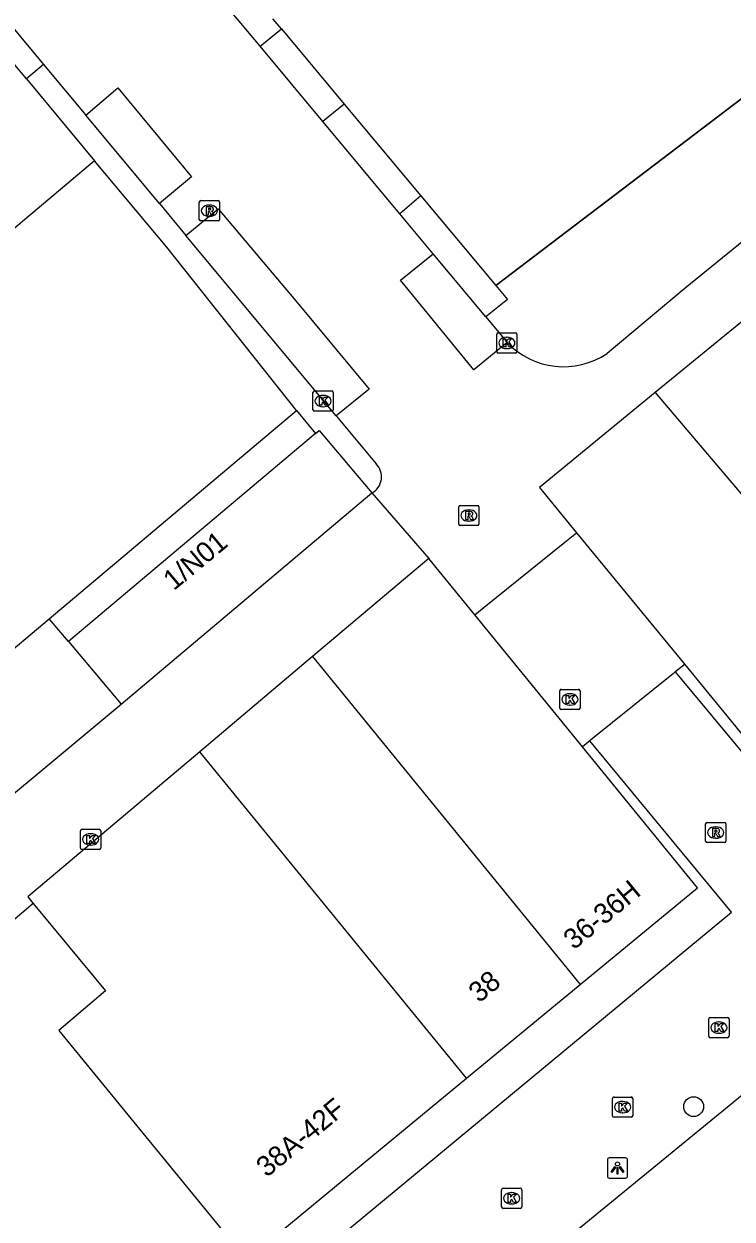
# Model space of a CAD drawing. Extents: x 161087 to 161922, y 382574 to 383873.
# Drawn here: x 161314.7 to 161349.7, y 383087.7 to 383146.8 of the extents above; entities that cross this region are included whole.
import ezdxf

# ---------------------------------------------------------------- set-up
doc = ezdxf.new("R2010")
doc.units = 0
for name, color, linetype in [('IMGEO_Boom', 7, 'Continuous'), ('IMGEO_Kolk', 7, 'Continuous'), ('IMGEO_Lichtpunt', 7, 'Continuous'), ('IMGEO_Muur', 7, 'Continuous'), ('IMGEO_Pand', 7, 'Continuous'), ('IMGEO_Pand_nummerreeks', 7, 'Continuous'), ('IMGEO_Parkeervlak_open', 7, 'Continuous'), ('IMGEO_Rijbaan_lokaal_open', 7, 'Continuous'), ('IMGEO_Rioolput', 7, 'Continuous'), ('IMGEO_Voetgangersgebied_open', 7, 'Continuous'), ('IMGEO_Voetpad_open', 7, 'Continuous')]:
    doc.layers.add(name, color=color, linetype=linetype)

msp = doc.modelspace()

# ---------------------------------------------------------------- linework, layer by layer
at = {"layer": 'IMGEO_Boom'}
msp.add_circle((161347.806, 383093.222), 0.489, dxfattribs=at)
at = {"layer": 'IMGEO_Kolk'}
for p, q in [((161338.063, 383130.574), (161338.063, 383131.426)), ((161338.138, 383131.5), (161338.99, 383131.5)), ((161339.064, 383131.426), (161339.064, 383130.574)), ((161338.551, 383131.28), (161338.576, 383131.28)), ((161338.99, 383130.5), (161338.138, 383130.5)), ((161338.574, 383130.72), (161338.549, 383130.72)), ((161328.969, 383127.696), (161328.969, 383128.548)), ((161329.044, 383128.622), (161329.896, 383128.622)), ((161329.457, 383128.402), (161329.482, 383128.402)), ((161329.97, 383128.548), (161329.97, 383127.696)), ((161329.48, 383127.842), (161329.455, 383127.842)), ((161329.896, 383127.622), (161329.044, 383127.622)), ((161341.182, 383112.938), (161341.182, 383113.79)), ((161341.257, 383113.864), (161342.109, 383113.864)), ((161341.67, 383113.644), (161341.695, 383113.644)), ((161342.183, 383113.79), (161342.183, 383112.938)), ((161341.693, 383113.084), (161341.668, 383113.084)), ((161342.109, 383112.864), (161341.257, 383112.864)), ((161317.467, 383106.014), (161317.467, 383106.866)), ((161317.542, 383106.94), (161318.394, 383106.94)), ((161317.955, 383106.72), (161317.98, 383106.72)), ((161318.468, 383106.866), (161318.468, 383106.014)), ((161318.394, 383105.94), (161317.542, 383105.94)), ((161317.978, 383106.16), (161317.953, 383106.16)), ((161348.631, 383097.633), (161349.483, 383097.633)), ((161348.556, 383096.707), (161348.556, 383097.559)), ((161349.044, 383097.413), (161349.069, 383097.413)), ((161349.557, 383097.559), (161349.557, 383096.707)), ((161349.483, 383096.633), (161348.631, 383096.633)), ((161349.067, 383096.853), (161349.042, 383096.853)), ((161343.792, 383092.773), (161343.792, 383093.625)), ((161343.867, 383093.699), (161344.719, 383093.699)), ((161344.793, 383093.625), (161344.793, 383092.773)), ((161344.303, 383092.919), (161344.278, 383092.919)), ((161344.28, 383093.479), (161344.305, 383093.479)), ((161344.719, 383092.699), (161343.867, 383092.699)), ((161338.301, 383088.263), (161338.301, 383089.115)), ((161338.376, 383089.189), (161339.228, 383089.189)), ((161338.789, 383088.969), (161338.814, 383088.969)), ((161339.302, 383089.115), (161339.302, 383088.263)), ((161339.228, 383088.189), (161338.376, 383088.189)), ((161338.812, 383088.409), (161338.787, 383088.409))]:
    msp.add_line(p, q, dxfattribs=at)
for points in [[(161338.063, 383130.574), (161338.063, 383131.426)], [(161338.138, 383131.5), (161338.99, 383131.5)], [(161339.064, 383131.426), (161339.064, 383130.574)], [(161338.384, 383131.2), (161338.507, 383131.2), (161338.507, 383131.049), (161338.637, 383131.2), (161338.801, 383131.2), (161338.655, 383131.049), (161338.808, 383130.8), (161338.656, 383130.8), (161338.571, 383130.964), (161338.507, 383130.897), (161338.507, 383130.8), (161338.384, 383130.8), (161338.384, 383131.2)], [(161338.99, 383130.5), (161338.138, 383130.5)], [(161328.969, 383127.696), (161328.969, 383128.548)], [(161329.044, 383128.622), (161329.896, 383128.622)], [(161329.97, 383128.548), (161329.97, 383127.696)], [(161329.29, 383128.322), (161329.413, 383128.322), (161329.413, 383128.171), (161329.543, 383128.322), (161329.707, 383128.322), (161329.561, 383128.171), (161329.714, 383127.922), (161329.562, 383127.922), (161329.477, 383128.086), (161329.413, 383128.019), (161329.413, 383127.922), (161329.29, 383127.922), (161329.29, 383128.322)], [(161329.896, 383127.622), (161329.044, 383127.622)], [(161341.182, 383112.938), (161341.182, 383113.79)], [(161341.257, 383113.864), (161342.109, 383113.864)], [(161342.183, 383113.79), (161342.183, 383112.938)], [(161341.503, 383113.564), (161341.626, 383113.564), (161341.626, 383113.413), (161341.756, 383113.564), (161341.92, 383113.564), (161341.774, 383113.413), (161341.927, 383113.164), (161341.775, 383113.164), (161341.69, 383113.328), (161341.626, 383113.261), (161341.626, 383113.164), (161341.503, 383113.164), (161341.503, 383113.564)], [(161342.109, 383112.864), (161341.257, 383112.864)], [(161317.467, 383106.014), (161317.467, 383106.866)], [(161317.542, 383106.94), (161318.394, 383106.94)], [(161317.788, 383106.64), (161317.911, 383106.64), (161317.911, 383106.489), (161318.041, 383106.64), (161318.205, 383106.64), (161318.059, 383106.489), (161318.212, 383106.24), (161318.06, 383106.24), (161317.975, 383106.404), (161317.911, 383106.337), (161317.911, 383106.24), (161317.788, 383106.24), (161317.788, 383106.64)], [(161318.468, 383106.866), (161318.468, 383106.014)], [(161318.394, 383105.94), (161317.542, 383105.94)], [(161348.631, 383097.633), (161349.483, 383097.633)], [(161348.556, 383096.707), (161348.556, 383097.559)], [(161348.877, 383097.333), (161349, 383097.333), (161349, 383097.182), (161349.13, 383097.333), (161349.294, 383097.333), (161349.148, 383097.182), (161349.301, 383096.933), (161349.149, 383096.933), (161349.064, 383097.097), (161349, 383097.03), (161349, 383096.933), (161348.877, 383096.933), (161348.877, 383097.333)], [(161349.557, 383097.559), (161349.557, 383096.707)], [(161349.483, 383096.633), (161348.631, 383096.633)], [(161343.792, 383092.773), (161343.792, 383093.625)], [(161343.867, 383093.699), (161344.719, 383093.699)], [(161344.793, 383093.625), (161344.793, 383092.773)], [(161344.113, 383093.399), (161344.236, 383093.399), (161344.236, 383093.248), (161344.366, 383093.399), (161344.53, 383093.399), (161344.384, 383093.248), (161344.537, 383092.999), (161344.385, 383092.999), (161344.3, 383093.163), (161344.236, 383093.096), (161344.236, 383092.999), (161344.113, 383092.999), (161344.113, 383093.399)], [(161344.719, 383092.699), (161343.867, 383092.699)], [(161338.301, 383088.263), (161338.301, 383089.115)], [(161338.376, 383089.189), (161339.228, 383089.189)], [(161338.622, 383088.889), (161338.745, 383088.889), (161338.745, 383088.738), (161338.875, 383088.889), (161339.039, 383088.889), (161338.893, 383088.738), (161339.046, 383088.489), (161338.894, 383088.489), (161338.809, 383088.653), (161338.745, 383088.586), (161338.745, 383088.489), (161338.622, 383088.489), (161338.622, 383088.889)], [(161339.302, 383089.115), (161339.302, 383088.263)], [(161339.228, 383088.189), (161338.376, 383088.189)]]:
    msp.add_lwpolyline(points, dxfattribs=at)
for centre, start, end in [((161338.14, 383131.424), 91.55205, 178.44795), ((161338.14, 383131.424), 91.55205, 178.44795), ((161338.988, 383131.424), 1.55205, 88.44795), ((161338.988, 383131.424), 1.55205, 88.44795), ((161338.14, 383130.576), 181.55205, 268.44795), ((161338.14, 383130.576), 181.55205, 268.44795), ((161338.988, 383130.576), 271.55205, 358.44795), ((161338.988, 383130.576), 271.55205, 358.44795), ((161329.046, 383128.546), 91.55205, 178.44795), ((161329.046, 383128.546), 91.55205, 178.44795), ((161329.894, 383128.546), 1.55205, 88.44795), ((161329.894, 383128.546), 1.55205, 88.44795), ((161329.046, 383127.698), 181.55205, 268.44795), ((161329.046, 383127.698), 181.55205, 268.44795), ((161329.894, 383127.698), 271.55205, 358.44795), ((161329.894, 383127.698), 271.55205, 358.44795), ((161341.259, 383113.788), 91.55205, 178.44795), ((161341.259, 383113.788), 91.55205, 178.44795), ((161342.107, 383113.788), 1.55205, 88.44795), ((161342.107, 383113.788), 1.55205, 88.44795), ((161341.259, 383112.94), 181.55205, 268.44795), ((161341.259, 383112.94), 181.55205, 268.44795), ((161342.107, 383112.94), 271.55205, 358.44795), ((161342.107, 383112.94), 271.55205, 358.44795), ((161317.544, 383106.864), 91.55205, 178.44795), ((161317.544, 383106.864), 91.55205, 178.44795), ((161318.392, 383106.864), 1.55205, 88.44795), ((161318.392, 383106.864), 1.55205, 88.44795), ((161317.544, 383106.016), 181.55205, 268.44795), ((161317.544, 383106.016), 181.55205, 268.44795), ((161318.392, 383106.016), 271.55205, 358.44795), ((161318.392, 383106.016), 271.55205, 358.44795), ((161348.633, 383097.557), 91.55205, 178.44795), ((161348.633, 383097.557), 91.55205, 178.44795), ((161349.481, 383097.557), 1.55205, 88.44795), ((161349.481, 383097.557), 1.55205, 88.44795), ((161348.633, 383096.709), 181.55205, 268.44795), ((161348.633, 383096.709), 181.55205, 268.44795), ((161349.481, 383096.709), 271.55205, 358.44795), ((161349.481, 383096.709), 271.55205, 358.44795), ((161343.869, 383093.623), 91.55205, 178.44795), ((161343.869, 383093.623), 91.55205, 178.44795), ((161344.717, 383093.623), 1.55205, 88.44795), ((161344.717, 383093.623), 1.55205, 88.44795), ((161343.869, 383092.775), 181.55205, 268.44795), ((161343.869, 383092.775), 181.55205, 268.44795), ((161344.717, 383092.775), 271.55205, 358.44795), ((161344.717, 383092.775), 271.55205, 358.44795), ((161338.378, 383089.113), 91.55205, 178.44795), ((161338.378, 383089.113), 91.55205, 178.44795), ((161339.226, 383089.113), 1.55205, 88.44795), ((161339.226, 383089.113), 1.55205, 88.44795), ((161338.378, 383088.265), 181.55205, 268.44795), ((161338.378, 383088.265), 181.55205, 268.44795), ((161339.226, 383088.265), 271.55205, 358.44795), ((161339.226, 383088.265), 271.55205, 358.44795)]:
    msp.add_arc(centre, 0.0765, start, end, dxfattribs=at)
for centre, major_axis, ratio, start_param, end_param in [((161338.55, 383131), (-0.387, 0.002), 0.722429, 4.712389, 7.853982), ((161338.575, 383131), (-0.39, 0.002), 0.717154, 1.570796, 4.712389), ((161329.456, 383128.122), (-0.387, 0.002), 0.722429, 4.712389, 7.853982), ((161329.481, 383128.122), (-0.39, 0.002), 0.717154, 1.570796, 4.712389), ((161341.669, 383113.364), (-0.387, 0.002), 0.722429, 4.712389, 7.853982), ((161341.694, 383113.364), (-0.39, 0.002), 0.717154, 1.570796, 4.712389), ((161317.954, 383106.44), (-0.387, 0.002), 0.722429, 4.712389, 7.853982), ((161317.979, 383106.44), (-0.39, 0.002), 0.717154, 1.570796, 4.712389), ((161349.043, 383097.133), (-0.387, 0.002), 0.722429, 4.712389, 7.853982), ((161349.068, 383097.133), (-0.39, 0.002), 0.717154, 1.570796, 4.712389), ((161344.279, 383093.199), (-0.387, 0.002), 0.722429, 4.712389, 7.853982), ((161344.304, 383093.199), (-0.39, 0.002), 0.717154, 1.570796, 4.712389), ((161338.788, 383088.689), (-0.387, 0.002), 0.722429, 4.712389, 7.853982), ((161338.813, 383088.689), (-0.39, 0.002), 0.717154, 1.570796, 4.712389)]:
    msp.add_ellipse(centre, major_axis=major_axis, ratio=ratio, start_param=start_param, end_param=end_param, dxfattribs=at)
at = {"layer": 'IMGEO_Lichtpunt'}
for p, q in [((161343.539, 383090.591), (161343.539, 383089.784)), ((161343.539, 383090.591), (161343.539, 383089.784)), ((161344.441, 383090.686), (161343.633, 383090.686)), ((161344.441, 383090.686), (161343.633, 383090.686)), ((161344.535, 383089.784), (161344.535, 383090.591)), ((161344.535, 383089.784), (161344.535, 383090.591)), ((161343.633, 383089.69), (161344.441, 383089.69)), ((161343.633, 383089.69), (161344.441, 383089.69))]:
    msp.add_line(p, q, dxfattribs=at)
for points in [[(161343.913, 383090.255), (161343.952, 383090.227), (161343.764, 383089.965), (161343.726, 383089.992), (161343.913, 383090.255)], [(161344.015, 383090.207), (161344.062, 383090.207), (161344.062, 383089.885), (161344.015, 383089.885), (161344.015, 383090.207)], [(161344.125, 383090.227), (161344.163, 383090.254), (161344.35, 383089.992), (161344.311, 383089.964), (161344.125, 383090.227)]]:
    msp.add_lwpolyline(points, dxfattribs=at)
msp.add_circle((161344.038, 383090.389), 0.0994, dxfattribs=at)
for centre, start, end in [((161343.633, 383090.591), 90, 180), ((161343.633, 383090.591), 90, 180), ((161344.441, 383090.591), 0, 90), ((161344.441, 383090.591), 0, 90), ((161343.633, 383089.784), 180, 270), ((161343.633, 383089.784), 180, 270), ((161344.441, 383089.784), 270, 0), ((161344.441, 383089.784), 270, 360)]:
    msp.add_arc(centre, 0.0946, start, end, dxfattribs=at)
at = {"layer": 'IMGEO_Muur'}
msp.add_lwpolyline([(161338.02, 383133.832), (161352.139, 383144.565)], dxfattribs=at)
at = {"layer": 'IMGEO_Pand'}
for points in [[(161318.155, 383140.007), (161303.657, 383127.806), (161297.243, 383122.411), (161296.75, 383123.041)], [(161328.147, 383127.651), (161321.746, 383135.741), (161318.155, 383140.007)], [(161351.5, 383133.112), (161345.91, 383128.541)], [(161345.91, 383128.541), (161340.173, 383123.848), (161342.01, 383121.612)], [(161345.91, 383128.541), (161356.619, 383115.911)], [(161315.91, 383117.352), (161328.147, 383127.651)], [(161329.098, 383126.516), (161329.283, 383126.672), (161331.884, 383123.579)], [(161329.098, 383126.516), (161316.874, 383116.227)], [(161319.475, 383113.135), (161331.884, 383123.579)], [(161342.01, 383121.612), (161347.363, 383115.097)], [(161334.699, 383120.333), (161328.949, 383115.484)], [(161336.976, 383117.545), (161334.699, 383120.333)], [(161306.597, 383109.514), (161315.91, 383117.352)], [(161342.3, 383111.027), (161342.167, 383111.191), (161336.976, 383117.545)], [(161316.874, 383116.227), (161319.475, 383113.135)], [(161328.949, 383115.484), (161323.371, 383110.78)], [(161328.949, 383115.484), (161342.197, 383099.261)], [(161347.363, 383115.097), (161348.48, 383113.738), (161349.746, 383112.193), (161350.691, 383111.04), (161353.296, 383113.18)], [(161323.371, 383110.78), (161314.857, 383103.599), (161315.131, 383103.273)], [(161336.573, 383094.624), (161323.371, 383110.78)], [(161342.197, 383099.261), (161348.002, 383104.048), (161342.3, 383111.027)], [(161315.131, 383103.273), (161312.979, 383101.462)], [(161315.131, 383103.273), (161318.705, 383098.955), (161316.388, 383096.985), (161325.68, 383085.643)], [(161336.573, 383094.624), (161342.197, 383099.261)], [(161325.68, 383085.643), (161336.573, 383094.624)]]:
    msp.add_lwpolyline(points, dxfattribs=at)
at = {"layer": 'IMGEO_Parkeervlak_open'}
for points in [[(161352.139, 383144.565), (161338.02, 383133.832)], [(161337.522, 383132.286), (161338.578, 383131.016)]]:
    msp.add_lwpolyline(points, dxfattribs=at)
at = {"layer": 'IMGEO_Rijbaan_lokaal_open'}
for points in [[(161311.777, 383149.418), (161315.642, 383144.775)], [(161326.36, 383145.671), (161323.832, 383148.703), (161323.335, 383149.299)], [(161329.465, 383141.948), (161326.36, 383145.671)], [(161315.642, 383144.775), (161317.729, 383142.268)], [(161317.729, 383142.268), (161319.315, 383143.611), (161322.96, 383139.22), (161321.375, 383137.889)], [(161333.271, 383137.384), (161329.465, 383141.948)], [(161355.558, 383140.385), (161351.874, 383137.347), (161347.38, 383133.706), (161343.527, 383130.482)], [(161321.375, 383137.889), (161322.685, 383136.315)], [(161322.685, 383136.315), (161324.276, 383137.635), (161328.101, 383133.1), (161331.755, 383128.708), (161330.12, 383127.386)], [(161334.914, 383135.414), (161333.271, 383137.384)], [(161338.578, 383131.016), (161336.936, 383129.67), (161333.299, 383134.098), (161334.914, 383135.414)], [(161330.12, 383127.386), (161332.094, 383125.015)], [(161331.884, 383123.579), (161334.699, 383120.333)], [(161336.976, 383117.545), (161337.445, 383117.924), (161341.44, 383121.151), (161342.01, 383121.612)], [(161347.363, 383115.097), (161346.896, 383114.722)], [(161346.896, 383114.722), (161346.807, 383114.65), (161342.789, 383111.42), (161342.668, 383111.323)], [(161309.985, 383105.238), (161319.475, 383113.135)], [(161342.668, 383111.323), (161342.3, 383111.027)], [(161357.76, 383102.637), (161353.934, 383096.833), (161331.379, 383078.376), (161324.754, 383073.591), (161319.89, 383069.645)]]:
    msp.add_lwpolyline(points, dxfattribs=at)
for centre, radius, start, end in [((161341.369, 383133.684), 3.861, 223.7046, 303.97855), ((161331.47, 383124.373), 0.895, 297.52711, 45.83303)]:
    msp.add_arc(centre, radius, start, end, dxfattribs=at)
at = {"layer": 'IMGEO_Rioolput'}
for p, q in [((161323.345, 383137.111), (161323.345, 383137.963)), ((161323.42, 383138.037), (161324.272, 383138.037)), ((161324.346, 383137.963), (161324.346, 383137.111)), ((161323.856, 383137.257), (161323.831, 383137.257)), ((161323.833, 383137.817), (161323.858, 383137.817)), ((161324.272, 383137.037), (161323.42, 383137.037)), ((161336.182, 383122.037), (161336.182, 383122.889)), ((161336.257, 383122.963), (161337.109, 383122.963)), ((161336.67, 383122.743), (161336.695, 383122.743)), ((161337.183, 383122.889), (161337.183, 383122.037)), ((161337.109, 383121.963), (161336.257, 383121.963)), ((161336.693, 383122.183), (161336.668, 383122.183)), ((161348.395, 383106.355), (161348.395, 383107.207)), ((161348.47, 383107.281), (161349.322, 383107.281)), ((161349.396, 383107.207), (161349.396, 383106.355)), ((161348.906, 383106.501), (161348.881, 383106.501)), ((161348.883, 383107.061), (161348.908, 383107.061)), ((161349.322, 383106.281), (161348.47, 383106.281))]:
    msp.add_line(p, q, dxfattribs=at)
for points in [[(161323.345, 383137.111), (161323.345, 383137.963)], [(161323.42, 383138.037), (161324.272, 383138.037)], [(161324.346, 383137.963), (161324.346, 383137.111)], [(161323.934, 383137.735), (161323.682, 383137.737), (161323.682, 383137.337)], [(161323.682, 383137.337), (161323.806, 383137.337), (161323.806, 383137.499), (161323.817, 383137.499)], [(161323.86, 383137.656), (161323.806, 383137.656), (161323.806, 383137.575)], [(161323.806, 383137.575), (161323.858, 383137.575)], [(161323.864, 383137.47), (161323.935, 383137.337), (161324.075, 383137.337), (161324.01, 383137.463)], [(161324.272, 383137.037), (161323.42, 383137.037)], [(161336.182, 383122.037), (161336.182, 383122.889)], [(161336.257, 383122.963), (161337.109, 383122.963)], [(161336.771, 383122.661), (161336.519, 383122.663), (161336.519, 383122.263)], [(161336.697, 383122.582), (161336.643, 383122.582), (161336.643, 383122.501)], [(161336.643, 383122.501), (161336.695, 383122.501)], [(161337.183, 383122.889), (161337.183, 383122.037)], [(161337.109, 383121.963), (161336.257, 383121.963)], [(161336.519, 383122.263), (161336.643, 383122.263), (161336.643, 383122.425), (161336.654, 383122.425)], [(161336.701, 383122.396), (161336.772, 383122.263), (161336.912, 383122.263), (161336.847, 383122.389)], [(161348.395, 383106.355), (161348.395, 383107.207)], [(161348.47, 383107.281), (161349.322, 383107.281)], [(161349.396, 383107.207), (161349.396, 383106.355)], [(161348.984, 383106.979), (161348.732, 383106.981), (161348.732, 383106.581)], [(161348.732, 383106.581), (161348.856, 383106.581), (161348.856, 383106.743), (161348.867, 383106.743)], [(161348.91, 383106.9), (161348.856, 383106.9), (161348.856, 383106.819)], [(161348.856, 383106.819), (161348.908, 383106.819)], [(161348.914, 383106.714), (161348.985, 383106.581), (161349.125, 383106.581), (161349.06, 383106.707)], [(161349.322, 383106.281), (161348.47, 383106.281)]]:
    msp.add_lwpolyline(points, dxfattribs=at)
for centre, radius, start, end in [((161323.422, 383137.961), 0.0765, 91.55205, 178.44795), ((161323.422, 383137.961), 0.0765, 91.55205, 178.44795), ((161324.27, 383137.961), 0.0765, 1.55205, 88.44795), ((161324.27, 383137.961), 0.0765, 1.55205, 88.44795), ((161323.816, 383137.446), 0.0533, 26.02933, 88.69889), ((161323.842, 383137.764), 0.19, 274.7715, 282.96867), ((161323.866, 383137.56), 0.0964, 77.00612, 93.18647), ((161323.88, 383137.617), 0.0378, 276.66336, 79.67722), ((161323.933, 383137.625), 0.109, 350.36119, 89.41601), ((161323.931, 383137.625), 0.112, 277.58423, 350.98172), ((161323.915, 383137.41), 0.108, 29.51342, 73.79051), ((161323.422, 383137.113), 0.0765, 181.55205, 268.44795), ((161323.422, 383137.113), 0.0765, 181.55205, 268.44795), ((161324.27, 383137.113), 0.0765, 271.55205, 358.44795), ((161324.27, 383137.113), 0.0765, 271.55205, 358.44795), ((161336.259, 383122.887), 0.0765, 91.55205, 178.44795), ((161336.259, 383122.887), 0.0765, 91.55205, 178.44795), ((161336.679, 383122.69), 0.19, 274.7715, 282.96867), ((161336.703, 383122.486), 0.0964, 77.00612, 93.18647), ((161336.717, 383122.543), 0.0378, 276.66336, 79.67722), ((161336.77, 383122.551), 0.109, 350.36119, 89.41601), ((161336.768, 383122.551), 0.112, 277.58423, 350.98172), ((161337.107, 383122.887), 0.0765, 1.55205, 88.44795), ((161337.107, 383122.887), 0.0765, 1.55205, 88.44795), ((161336.259, 383122.039), 0.0765, 181.55205, 268.44795), ((161336.259, 383122.039), 0.0765, 181.55205, 268.44795), ((161336.653, 383122.372), 0.0533, 26.02933, 88.69889), ((161336.752, 383122.336), 0.108, 29.51342, 73.79051), ((161337.107, 383122.039), 0.0765, 271.55205, 358.44795), ((161337.107, 383122.039), 0.0765, 271.55205, 358.44795), ((161348.472, 383107.205), 0.0765, 91.55205, 178.44795), ((161348.472, 383107.205), 0.0765, 91.55205, 178.44795), ((161349.32, 383107.205), 0.0765, 1.55205, 88.44795), ((161349.32, 383107.205), 0.0765, 1.55205, 88.44795), ((161348.866, 383106.69), 0.0533, 26.02933, 88.69889), ((161348.892, 383107.008), 0.19, 274.7715, 282.96867), ((161348.916, 383106.804), 0.0964, 77.00612, 93.18647), ((161348.93, 383106.861), 0.0378, 276.66336, 79.67722), ((161348.983, 383106.869), 0.109, 350.36119, 89.41601), ((161348.981, 383106.869), 0.112, 277.58423, 350.98172), ((161348.965, 383106.654), 0.108, 29.51342, 73.79051), ((161348.472, 383106.357), 0.0765, 181.55205, 268.44795), ((161348.472, 383106.357), 0.0765, 181.55205, 268.44795), ((161349.32, 383106.357), 0.0765, 271.55205, 358.44795), ((161349.32, 383106.357), 0.0765, 271.55205, 358.44795)]:
    msp.add_arc(centre, radius, start, end, dxfattribs=at)
for centre, major_axis, ratio, start_param, end_param in [((161323.832, 383137.537), (-0.387, 0.002), 0.722429, 4.712389, 7.853982), ((161323.857, 383137.537), (-0.39, 0.002), 0.717154, 1.570796, 4.712389), ((161336.669, 383122.463), (-0.387, 0.002), 0.722429, 4.712389, 7.853982), ((161336.694, 383122.463), (-0.39, 0.002), 0.717154, 1.570796, 4.712389), ((161348.882, 383106.781), (-0.387, 0.002), 0.722429, 4.712389, 7.853982), ((161348.907, 383106.781), (-0.39, 0.002), 0.717154, 1.570796, 4.712389)]:
    msp.add_ellipse(centre, major_axis=major_axis, ratio=ratio, start_param=start_param, end_param=end_param, dxfattribs=at)
at = {"layer": 'IMGEO_Voetgangersgebied_open'}
for points in [[(161346.896, 383114.722), (161350.565, 383110.309), (161353.567, 383112.777)], [(161315.817, 383074.812), (161349.672, 383102.844), (161342.668, 383111.323)]]:
    msp.add_lwpolyline(points, dxfattribs=at)
at = {"layer": 'IMGEO_Voetpad_open'}
for points in [[(161314.789, 383144.056), (161310.902, 383148.73)], [(161327.407, 383146.528), (161326.987, 383147.03)], [(161326.36, 383145.671), (161327.407, 383146.528)], [(161327.407, 383146.528), (161330.518, 383142.806)], [(161315.642, 383144.775), (161314.789, 383144.056)], [(161314.789, 383144.056), (161318.155, 383140.007)], [(161330.518, 383142.806), (161329.465, 383141.948)], [(161330.518, 383142.806), (161334.311, 383138.269)], [(161321.375, 383137.889), (161317.729, 383142.268)], [(161334.311, 383138.269), (161333.271, 383137.384)], [(161334.311, 383138.269), (161338.02, 383133.832)], [(161330.12, 383127.386), (161322.685, 383136.315)], [(161337.522, 383132.286), (161334.914, 383135.414)], [(161338.02, 383133.832), (161338.597, 383133.149), (161337.522, 383132.286)], [(161328.147, 383127.651), (161329.098, 383126.516)], [(161316.874, 383116.227), (161315.91, 383117.352)]]:
    msp.add_lwpolyline(points, dxfattribs=at)

# ---------------------------------------------------------------- texts
at = {"layer": 'IMGEO_Pand_nummerreeks'}
for s, rotation, p in [('1/N01', 39.57826, (161322.081, 383118.717)), ('36-36H', 39.51117, (161341.881, 383100.945)), ('38', 39.39514, (161337.189, 383098.319)), ('38A-42F', 39.39688, (161326.684, 383089.692))]:
    msp.add_text(s, height=1, rotation=rotation, dxfattribs=at).set_placement(p)

doc.saveas('drawing.dxf')
